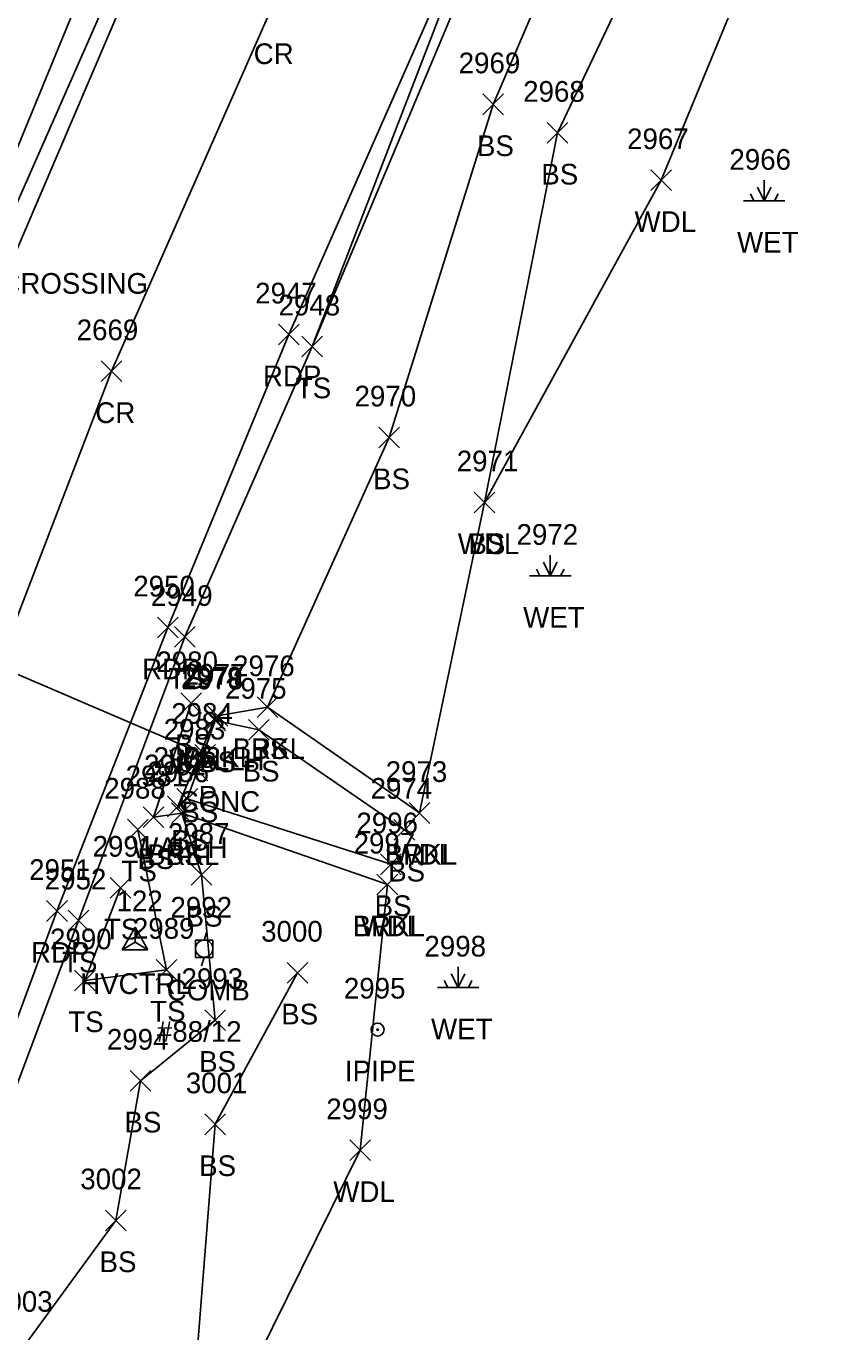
# Model space of a CAD drawing. Extents: x 1678863 to 1683592, y 407783 to 418211.
# Drawn here: x 1680560.9 to 1680639, y 415379.6 to 415505.8 of the extents above; entities that cross this region are included whole.
import ezdxf

# ---------------------------------------------------------------- set-up
doc = ezdxf.new("R2010")
doc.units = 0
for name, color, linetype in [('C_A', 7, 'Continuous'), ('C_I', 7, 'Continuous'), ('CPSM', 7, 'Continuous'), ('D_A', 7, 'Continuous'), ('D_C', 7, 'Continuous'), ('D_I', 7, 'Continuous'), ('D_TIC', 7, 'Continuous'), ('DCP', 7, 'Continuous'), ('DHW', 7, 'Continuous'), ('L_A', 7, 'Continuous'), ('L_I', 7, 'Continuous'), ('L_TIC', 7, 'Continuous'), ('LAWA', 7, 'Continuous'), ('LAWE', 7, 'Continuous'), ('LELB', 7, 'Continuous'), ('LWET', 7, 'Continuous'), ('M_A', 7, 'Continuous'), ('M_I', 7, 'Continuous'), ('MPIP', 7, 'Continuous'), ('P_A', 7, 'Continuous'), ('P_I', 7, 'Continuous'), ('P_TIC', 7, 'Continuous'), ('PET', 7, 'Continuous'), ('PRC', 7, 'Continuous'), ('S_C', 7, 'Continuous'), ('U_A', 7, 'Continuous'), ('U_C', 7, 'Continuous'), ('U_I', 7, 'Continuous'), ('UP', 7, 'Continuous')]:
    doc.layers.add(name, color=color, linetype=linetype)

msp = doc.modelspace()

# ---------------------------------------------------------------- linework, layer by layer
at = {"layer": 'CPSM'}
for p, q in [((1680570.18, 415416.57), (1680571.43, 415418.74)), ((1680570.18, 415416.57), (1680571.43, 415418.74)), ((1680572.68, 415416.57), (1680571.43, 415418.74)), ((1680571.44, 415417.29), (1680571.43, 415418.74)), ((1680572.68, 415416.57), (1680571.43, 415418.74)), ((1680571.44, 415417.29), (1680571.43, 415418.74)), ((1680570.18, 415416.57), (1680571.44, 415417.29)), ((1680570.18, 415416.57), (1680571.44, 415417.29)), ((1680571.44, 415417.29), (1680571.44, 415417.29)), ((1680571.44, 415417.29), (1680572.68, 415416.57)), ((1680571.44, 415417.29), (1680571.44, 415417.29)), ((1680571.44, 415417.29), (1680572.68, 415416.57)), ((1680570.18, 415416.57), (1680572.68, 415416.57)), ((1680570.18, 415416.57), (1680572.68, 415416.57))]:
    msp.add_line(p, q, dxfattribs=at)
at = {"layer": 'D_TIC'}
for points in [[(1680578.13, 415437.89), (1680580.13, 415439.89)], [(1680580.13, 415437.89), (1680578.13, 415439.89)], [(1680577.19, 415434.4), (1680579.19, 415436.4)], [(1680579.19, 415434.4), (1680577.19, 415436.4)], [(1680574.56, 415429.42), (1680576.56, 415431.42)], [(1680576.56, 415429.42), (1680574.56, 415431.42)]]:
    msp.add_lwpolyline(points, dxfattribs=at)
at = {"layer": 'DCP'}
msp.add_lwpolyline([(1680543.65, 415450.23), (1680578.19, 415435.4)], dxfattribs=at)
at = {"layer": 'DHW'}
msp.add_lwpolyline([(1680579.13, 415438.89), (1680575.56, 415430.42)], dxfattribs=at)
at = {"layer": 'L_TIC'}
for points in [[(1680605.01, 415497.25), (1680607.01, 415499.25)], [(1680607.01, 415497.25), (1680605.01, 415499.25)], [(1680611.23, 415494.5), (1680613.23, 415496.5)], [(1680613.23, 415494.5), (1680611.23, 415496.5)], [(1680621.26, 415489.92), (1680623.26, 415491.92)], [(1680623.26, 415489.92), (1680621.26, 415491.92)], [(1680587.55, 415473.85), (1680589.55, 415475.85)], [(1680589.55, 415473.85), (1680587.55, 415475.85)], [(1680587.55, 415473.85), (1680589.55, 415475.85)], [(1680589.55, 415473.85), (1680587.55, 415475.85)], [(1680594.98, 415465.06), (1680596.98, 415467.06)], [(1680596.98, 415465.06), (1680594.98, 415467.06)], [(1680604.19, 415458.79), (1680606.19, 415460.79)], [(1680606.19, 415458.79), (1680604.19, 415460.79)], [(1680604.19, 415458.79), (1680606.19, 415460.79)], [(1680606.19, 415458.79), (1680604.19, 415460.79)], [(1680575.23, 415445.79), (1680577.23, 415447.79)], [(1680577.23, 415445.79), (1680575.23, 415447.79)], [(1680575.84, 415439.39), (1680577.84, 415441.39)], [(1680577.84, 415439.39), (1680575.84, 415441.39)], [(1680583.22, 415439), (1680585.22, 415441)], [(1680585.22, 415439), (1680583.22, 415441)], [(1680583.22, 415439), (1680585.22, 415441)], [(1680585.22, 415439), (1680583.22, 415441)], [(1680578.18, 415437.72), (1680580.18, 415439.72)], [(1680580.18, 415437.72), (1680578.18, 415439.72)], [(1680578.39, 415438.18), (1680580.39, 415440.18)], [(1680580.39, 415438.18), (1680578.39, 415440.18)], [(1680582.38, 415436.82), (1680584.38, 415438.82)], [(1680584.38, 415436.82), (1680582.38, 415438.82)], [(1680576.46, 415432.88), (1680578.46, 415434.88)], [(1680578.46, 415432.88), (1680576.46, 415434.88)], [(1680575.48, 415430.14), (1680577.48, 415432.14)], [(1680577.48, 415430.14), (1680575.48, 415432.14)], [(1680572.21, 415428.37), (1680574.21, 415430.37)], [(1680574.21, 415428.37), (1680572.21, 415430.37)], [(1680574.94, 415428.76), (1680576.94, 415430.76)], [(1680576.94, 415428.76), (1680574.94, 415430.76)], [(1680574.94, 415428.76), (1680576.94, 415430.76)], [(1680576.94, 415428.76), (1680574.94, 415430.76)], [(1680597.9, 415428.78), (1680599.9, 415430.78)], [(1680599.9, 415428.78), (1680597.9, 415430.78)], [(1680597.9, 415428.78), (1680599.9, 415430.78)], [(1680599.9, 415428.78), (1680597.9, 415430.78)], [(1680570.71, 415427.17), (1680572.71, 415429.17)], [(1680572.71, 415427.17), (1680570.71, 415429.17)], [(1680596.44, 415427.16), (1680598.44, 415429.16)], [(1680598.44, 415427.16), (1680596.44, 415429.16)], [(1680595.13, 415423.82), (1680597.13, 415425.82)], [(1680597.13, 415423.82), (1680595.13, 415425.82)], [(1680576.86, 415422.8), (1680578.86, 415424.8)], [(1680578.86, 415422.8), (1680576.86, 415424.8)], [(1680569.02, 415421.56), (1680571.02, 415423.56)], [(1680571.02, 415421.56), (1680569.02, 415423.56)], [(1680594.8, 415421.86), (1680596.8, 415423.86)], [(1680596.8, 415421.86), (1680594.8, 415423.86)], [(1680594.8, 415421.86), (1680596.8, 415423.86)], [(1680596.8, 415421.86), (1680594.8, 415423.86)], [(1680564.97, 415418.39), (1680566.97, 415420.39)], [(1680566.97, 415418.39), (1680564.97, 415420.39)], [(1680565.57, 415412.61), (1680567.57, 415414.61)], [(1680567.57, 415412.61), (1680565.57, 415414.61)], [(1680573.48, 415413.63), (1680575.48, 415415.63)], [(1680575.48, 415413.63), (1680573.48, 415415.63)], [(1680586.11, 415413.35), (1680588.11, 415415.35)], [(1680588.11, 415413.35), (1680586.11, 415415.35)], [(1680578.18, 415408.77), (1680580.18, 415410.77)], [(1680580.18, 415408.77), (1680578.18, 415410.77)], [(1680570.97, 415402.91), (1680572.97, 415404.91)], [(1680572.97, 415402.91), (1680570.97, 415404.91)], [(1680578.18, 415398.7), (1680580.18, 415400.7)], [(1680580.18, 415398.7), (1680578.18, 415400.7)], [(1680592.17, 415396.19), (1680594.17, 415398.19)], [(1680594.17, 415396.19), (1680592.17, 415398.19)], [(1680568.56, 415389.42), (1680570.56, 415391.42)], [(1680570.56, 415389.42), (1680568.56, 415391.42)]]:
    msp.add_lwpolyline(points, dxfattribs=at)
at = {"layer": 'LAWA'}
for points in [[(1680734.88, 415676.75), (1680712.01, 415650.49), (1680695.42, 415626.04), (1680674.18, 415601.42), (1680654.67, 415569.26), (1680640.03, 415533.99), (1680622.26, 415490.92), (1680605.19, 415459.79), (1680598.9, 415429.78)], [(1680595.8, 415422.86), (1680593.17, 415397.19), (1680576.28, 415363)]]:
    msp.add_lwpolyline(points, dxfattribs=at)
at = {"layer": 'LAWE'}
for points in [[(1680598.9, 415429.78), (1680584.22, 415440), (1680579.39, 415439.18)], [(1680575.94, 415429.76), (1680595.8, 415422.86)]]:
    msp.add_lwpolyline(points, dxfattribs=at)
at = {"layer": 'LELB'}
for points in [[(1680779.02, 415827.07), (1680764.6, 415800.72), (1680749.76, 415782.11), (1680734.08, 415752.62), (1680721.13, 415730.53), (1680704.81, 415692.99), (1680704.75, 415688.18), (1680689.04, 415667.71), (1680668.98, 415635.11), (1680668.13, 415633.15), (1680666.86, 415630.18), (1680666.01, 415629.15), (1680664.53, 415626.69), (1680656.16, 415606.33), (1680642.64, 415571.64), (1680625.84, 415544.48), (1680606.01, 415498.25), (1680595.98, 415466.06), (1680584.22, 415440)], [(1680760.46, 415817.8), (1680759.2, 415806.58), (1680737.44, 415772.53), (1680718.55, 415734.23), (1680698.03, 415698.1), (1680678.91, 415660.83), (1680666.54, 415635.48), (1680651.21, 415608.56), (1680637.64, 415579.7), (1680620.72, 415545.75), (1680603.88, 415511.3), (1680588.55, 415474.85)], [(1680632.17, 415645.36), (1680615.45, 415613.7), (1680599.55, 415582.66), (1680582, 415541.28), (1680567.86, 415513.08), (1680554.53, 415480.69), (1680546.59, 415460.78), (1680542.6, 415453.6), (1680540.64, 415455.07)], [(1680633.35, 415643.72), (1680617.1, 415612.79), (1680602.64, 415581.48), (1680583.69, 415540.74), (1680570.36, 415512.19), (1680555.93, 415479.46), (1680544.79, 415450.21), (1680534.43, 415426.53), (1680521.07, 415388.59), (1680509.57, 415354.33), (1680496.9, 415318.18), (1680492.8, 415319.1)], [(1680667.35, 415605.37), (1680647.12, 415571.01), (1680633.39, 415540.01), (1680612.23, 415495.5), (1680605.19, 415459.79)], [(1680602.77, 415511.81), (1680588.55, 415474.85), (1680576.23, 415446.79), (1680565.97, 415419.39), (1680554.33, 415388.44), (1680545.73, 415364.19), (1680536.09, 415340.18), (1680525.46, 415304.97), (1680519.4, 415286.41), (1680524.68, 415282.14), (1680532.04, 415285.77), (1680542.28, 415291.47), (1680548.68, 415299.81), (1680553.8, 415323.68), (1680564.17, 415335.4), (1680560.17, 415349.32), (1680559.79, 415354.79), (1680578.2, 415359.45)], [(1680576.84, 415440.39), (1680573.21, 415429.37), (1680575.94, 415429.76), (1680577.86, 415423.8), (1680579.18, 415409.77), (1680571.97, 415403.91), (1680569.56, 415390.42), (1680560.94, 415378.59), (1680558.79, 415358.91)], [(1680597.44, 415428.16), (1680583.38, 415437.82), (1680579.18, 415438.72), (1680577.46, 415433.88), (1680576.48, 415431.14), (1680596.13, 415424.82)], [(1680571.71, 415428.17), (1680574.48, 415414.63), (1680566.57, 415413.61), (1680570.02, 415422.56)], [(1680587.11, 415414.35), (1680579.18, 415399.7), (1680576.28, 415363)]]:
    msp.add_lwpolyline(points, dxfattribs=at)
at = {"layer": 'LWET'}
for p, q in [((1680632.2, 415488.93), (1680631.54, 415490.26)), ((1680632.2, 415488.93), (1680632.2, 415490.93)), ((1680632.2, 415488.93), (1680632.87, 415490.26)), ((1680634.2, 415488.93), (1680630.2, 415488.93)), ((1680631.2, 415488.93), (1680630.87, 415489.6)), ((1680633.2, 415488.93), (1680633.54, 415489.6)), ((1680611.54, 415452.69), (1680610.87, 415454.02)), ((1680611.54, 415452.69), (1680611.54, 415454.69)), ((1680611.54, 415452.69), (1680612.21, 415454.02)), ((1680613.54, 415452.69), (1680609.54, 415452.69)), ((1680610.54, 415452.69), (1680610.21, 415453.35)), ((1680612.54, 415452.69), (1680612.87, 415453.35)), ((1680602.64, 415412.91), (1680602.64, 415414.91)), ((1680601.64, 415412.91), (1680601.3, 415413.58)), ((1680602.64, 415412.91), (1680601.97, 415414.24)), ((1680602.64, 415412.91), (1680603.3, 415414.24)), ((1680603.64, 415412.91), (1680603.97, 415413.58)), ((1680604.64, 415412.91), (1680600.64, 415412.91))]:
    msp.add_line(p, q, dxfattribs=at)
at = {"layer": 'MPIP'}
for radius in [0.625, 0.0833]:
    msp.add_circle((1680594.86, 415408.85), radius, dxfattribs=at)
at = {"layer": 'P_TIC'}
for points in [[(1680585.29, 415475.01), (1680587.29, 415477.01)], [(1680587.29, 415475.01), (1680585.29, 415477.01)], [(1680568.15, 415471.46), (1680570.15, 415473.46)], [(1680570.15, 415471.46), (1680568.15, 415473.46)], [(1680573.61, 415446.7), (1680575.61, 415448.7)], [(1680575.61, 415446.7), (1680573.61, 415448.7)], [(1680562.89, 415419.31), (1680564.89, 415421.31)], [(1680564.89, 415419.31), (1680562.89, 415421.31)]]:
    msp.add_lwpolyline(points, dxfattribs=at)
at = {"layer": 'PET'}
for points in [[(1680714.62, 415736.11), (1680695.56, 415699.43), (1680676.82, 415662.6), (1680663.45, 415636.86), (1680649.23, 415610.25), (1680634.13, 415580.72), (1680618.24, 415547.61), (1680602.16, 415512.05), (1680586.29, 415476.01), (1680574.61, 415447.7), (1680563.89, 415420.31), (1680552.33, 415389.01), (1680543.5, 415364.71), (1680535.14, 415340.61), (1680523.39, 415305.41), (1680517.77, 415286.76), (1680506.72, 415249.99), (1680495.8, 415211.55), (1680487.74, 415180.8)], [(1680674.8, 415719.5), (1680654.86, 415682.79), (1680638.98, 415649.62), (1680619.32, 415611.68), (1680604.15, 415580.83), (1680584.73, 415539.97), (1680571.82, 415511.9), (1680557.49, 415478.39), (1680544.08, 415445.87), (1680536.29, 415425.79), (1680523.06, 415388.11), (1680510.43, 415353.62), (1680497.85, 415315.66), (1680486.4, 415279.22), (1680483.29, 415266.82), (1680478.84, 415252.28), (1680468.22, 415214.69), (1680459.71, 415182.46)]]:
    msp.add_lwpolyline(points, dxfattribs=at)
at = {"layer": 'PRC'}
msp.add_lwpolyline([(1680684.22, 415706.23), (1680664.5, 415668.42), (1680651.65, 415643.03), (1680631.65, 415605.57), (1680617, 415575.83), (1680596.48, 415533.87), (1680584.46, 415507.14), (1680569.15, 415472.46), (1680556.96, 415440.74), (1680549.08, 415420.65), (1680536.22, 415384.73), (1680523.38, 415348.31), (1680512.19, 415314.3), (1680500.03, 415274.9), (1680490.66, 415243.58), (1680481.59, 415211.17), (1680473.06, 415178.67)], dxfattribs=at)
at = {"layer": 'UP'}
for p, q in [((1680578.36, 415418.33), (1680578.11, 415417.5)), ((1680577.27, 415415.83), (1680577.27, 415417.5)), ((1680577.27, 415417.5), (1680578.94, 415417.5)), ((1680578.94, 415417.5), (1680578.94, 415415.83)), ((1680578.94, 415415.83), (1680577.27, 415415.83)), ((1680577.86, 415415), (1680578.11, 415415.83)), ((1680578.11, 415416.67), (1680578.11, 415416.67))]:
    msp.add_line(p, q, dxfattribs=at)
msp.add_circle((1680578.11, 415416.67), 0.833, dxfattribs=at)

# ---------------------------------------------------------------- texts
at = {"layer": 'C_A'}
msp.add_text('HVCTRL', height=2, dxfattribs=at).set_placement((1680566.13, 415412.29))
msp.add_text('HVCTRL', height=2, dxfattribs=at).set_placement((1680566.13, 415412.29))
at = {"layer": 'C_I'}
msp.add_text('122', height=2, dxfattribs=at).set_placement((1680569.64, 415420.29))
msp.add_text('122', height=2, dxfattribs=at).set_placement((1680569.64, 415420.29))
at = {"layer": 'D_A'}
for s, p in [('WALLH', (1680574.72, 415433.89)), ('P', (1680577.57, 415430.4)), ('WALLH', (1680571.15, 415425.42))]:
    msp.add_text(s, height=2, dxfattribs=at).set_placement(p)
at = {"layer": 'D_C'}
msp.add_text('CONC', height=2, dxfattribs=at).set_placement((1680575.64, 415429.89))
at = {"layer": 'D_I'}
for s, p in [('2979', (1680575.86, 415441.89)), ('2984', (1680574.93, 415438.4)), ('2982', (1680572.3, 415433.42))]:
    msp.add_text(s, height=2, dxfattribs=at).set_placement(p)
at = {"layer": 'L_A'}
for s, p in [('BS', (1680604.45, 415493.25)), ('BS', (1680610.67, 415490.5)), ('WDL', (1680619.68, 415485.92)), ('WET', (1680629.58, 415483.93)), ('TS', (1680586.96, 415469.85)), ('TS', (1680586.96, 415469.85)), ('BS', (1680594.42, 415461.06)), ('WDL', (1680602.61, 415454.79)), ('BS', (1680603.63, 415454.79)), ('WET', (1680608.92, 415447.69)), ('TS', (1680574.64, 415441.79)), ('BS', (1680575.28, 415435.39)), ('BRKL', (1680576.03, 415434.18)), ('BRKL', (1680580.86, 415435)), ('BS', (1680582.66, 415435)), ('BS', (1680577.62, 415433.72)), ('BS', (1680581.82, 415432.82)), ('BS', (1680575.9, 415428.88)), ('BS', (1680574.92, 415426.14)), ('BS', (1680571.65, 415424.37)), ('BRKL', (1680572.59, 415424.76)), ('BS', (1680574.38, 415424.76)), ('BRKL', (1680595.55, 415424.78)), ('WDL', (1680596.32, 415424.78)), ('TS', (1680570.12, 415423.17)), ('BS', (1680595.88, 415423.16)), ('BS', (1680576.31, 415418.8)), ('BS', (1680594.57, 415419.82)), ('TS', (1680568.43, 415417.56)), ('BRKL', (1680592.45, 415417.86)), ('WDL', (1680593.22, 415417.86)), ('TS', (1680564.38, 415414.39)), ('TS', (1680564.98, 415408.61)), ('TS', (1680572.89, 415409.63)), ('BS', (1680585.55, 415409.35)), ('WET', (1680600.02, 415407.91)), ('BS', (1680577.62, 415404.77)), ('BS', (1680570.41, 415398.91)), ('BS', (1680577.62, 415394.7)), ('WDL', (1680590.58, 415392.19)), ('BS', (1680568, 415385.42))]:
    msp.add_text(s, height=2, dxfattribs=at).set_placement(p)
at = {"layer": 'L_I'}
for s, p in [('2969', (1680602.69, 415501.25)), ('2968', (1680608.92, 415498.5)), ('2967', (1680618.96, 415493.92)), ('2966', (1680628.84, 415491.93)), ('2948', (1680585.29, 415477.85)), ('2948', (1680585.29, 415477.85)), ('2970', (1680592.63, 415469.06)), ('2971', (1680602.5, 415462.79)), ('2971', (1680602.5, 415462.79)), ('2972', (1680608.28, 415455.69)), ('2949', (1680572.97, 415449.79)), ('2980', (1680573.49, 415443.39)), ('2976', (1680580.9, 415443)), ('2976', (1680580.9, 415443)), ('2978', (1680575.92, 415441.72)), ('2977', (1680576.13, 415442.18)), ('2975', (1680580.12, 415440.82)), ('2983', (1680574.2, 415436.88)), ('2985', (1680573.22, 415434.14)), ('2986', (1680572.63, 415432.76)), ('2986', (1680572.63, 415432.76)), ('2973', (1680595.64, 415432.78)), ('2973', (1680595.64, 415432.78)), ('2981', (1680570.52, 415432.37)), ('2988', (1680568.45, 415431.17)), ('2974', (1680594.18, 415431.16)), ('2996', (1680592.81, 415427.82)), ('2987', (1680574.6, 415426.8)), ('2991', (1680567.33, 415425.56)), ('2997', (1680592.54, 415425.86)), ('2997', (1680592.54, 415425.86)), ('2952', (1680562.71, 415422.39)), ('2989', (1680571.22, 415417.63)), ('2990', (1680563.22, 415416.61)), ('3000', (1680583.61, 415417.35)), ('2998', (1680599.38, 415415.91)), ('2993', (1680575.92, 415412.77)), ('2994', (1680568.71, 415406.91)), ('3001', (1680576.33, 415402.7)), ('2999', (1680589.9, 415400.19)), ('3002', (1680566.14, 415393.42)), ('3003', (1680557.52, 415381.59))]:
    msp.add_text(s, height=2, dxfattribs=at).set_placement(p)
at = {"layer": 'M_A'}
msp.add_text('IPIPE', height=2, dxfattribs=at).set_placement((1680591.7, 415403.85))
at = {"layer": 'M_I'}
msp.add_text('2995', height=2, dxfattribs=at).set_placement((1680591.6, 415411.85))
at = {"layer": 'P_A'}
for s, p in [('CR', (1680582.89, 415502.14)), ('RDP', (1680583.78, 415471.01)), ('CR', (1680567.59, 415467.46)), ('RDP', (1680572.1, 415442.7)), ('RDP', (1680561.38, 415415.31))]:
    msp.add_text(s, height=2, dxfattribs=at).set_placement(p)
at = {"layer": 'P_I'}
for s, p in [('2947', (1680583.03, 415479.01)), ('2669', (1680565.79, 415475.46)), ('2950', (1680571.26, 415450.7)), ('2951', (1680561.2, 415423.31))]:
    msp.add_text(s, height=2, dxfattribs=at).set_placement(p)
at = {"layer": 'S_C'}
msp.add_text('SNOWMOBILE CROSSING', height=2, dxfattribs=at).set_placement((1680539.25, 415479.95))
at = {"layer": 'U_A'}
msp.add_text('COMB', height=2, dxfattribs=at).set_placement((1680574.49, 415411.67))
at = {"layer": 'U_C'}
msp.add_text('#88/12', height=2, dxfattribs=at).set_placement((1680573.54, 415407.67))
at = {"layer": 'U_I'}
msp.add_text('2992', height=2, dxfattribs=at).set_placement((1680574.85, 415419.67))

doc.saveas('drawing.dxf')
